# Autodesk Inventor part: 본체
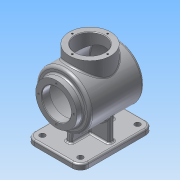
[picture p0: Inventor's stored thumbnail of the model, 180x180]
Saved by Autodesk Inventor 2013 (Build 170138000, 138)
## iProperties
Created: 2016-09
Part Number: 본체
Material: 알루미늄 6061
Document SubType Name: Modeling
Designer: Administrator
Density: 2.71 g/cm^3
Mass: 972.437 g
Surface Area: 1283.07 cm^2
Volume: 358.833 cm^3
Author: Administrator
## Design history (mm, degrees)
sketch "스케치1"
  geometry: L1 (-62, 38)-(-62, 27); L2 (-62, 27)-(-47, 27); L3 (-47, 27)-(-47, 47); L4 (-47, 47)-(46.661, 47); L5 (-62, 38)-(-50, 38); L6 (-50, 38)-(-50, 50); L7 (-50, 50)-(48.562, 50); L8 (57, 0)-(60, 0); A1 r 115 centre (-55, 0) between (60, 0) and (48.562, 50); A2 r 112 centre (-55, 0) between (57, 0) and (46.661, 47); 1 further point
  constraints: 16 end point, 4 parallel, 4 point on circle, 2 centre point, 2 perpendicular, 1 horizontal alignment, 1 point on line, 1 vertical
  dimensions: "d0" = 115 radius of A1; "d2" = 3 radial gap between concentric circles of A1 A2; "d3" = 54 diameter of L2 L8; "d4" = 76 diameter of L5 L8; "d5" = 100 diameter of L7 L8; "d6" = 94 diameter of L4 L8; "d7" = 15 distance between parallel lines of L3 L1; "d8" = 12 distance between parallel lines of L6 L1; "d9" = 110 distance from line of L8.end L6; "d51" = 50 distance from line of point (0, 0) L6
revolve "회전1" sketch "스케치1" stored, may be unused: angle "d11" = 90 deg
node "작업 평면1"
sketch "스케치2"
  geometry: L1 (50, 50)-(50, -50) reference; C1 r 38 at (0, 0); 1 further point
  constraints: 1 centre point, 1 coincident
  dimensions: "d13" = 76 diameter of C1; "d15" = 50 distance from line of C1.centre L1
extrude "돌출1" join sketch "스케치2" stored distance "d16" = 10; taper "d17" = 0 deg
hole "구멍1" diameter "d20" = 54; stored, may be unused: countersink angle "d24" = 90 deg, drill point angle "d26" = 118 deg; dims "d18" = 10, "d19" = 10, "d21" = 6, "d22" = 4, "d23" = 2, "d25" = 40
node "작업 평면2"
sketch "스케치6"
  geometry: L1 (-52.5, 50)-(52.5, 50); L2 (67.5, 35)-(67.5, -35); L3 (52.5, -50)-(-52.5, -50); L4 (-67.5, -35)-(-67.5, 35); C1 r 38 at (0, 0) reference; A1 r 15 centre (-52.5, 35) between (-52.5, 50) and (-67.5, 35); A2 r 15 centre (52.5, 35) between (67.5, 35) and (52.5, 50); A3 r 15 centre (52.5, -35) between (52.5, -50) and (67.5, -35); A4 r 15 centre (-52.5, -35) between (-67.5, -35) and (-52.5, -50); 3 further points
  constraints: 8 end point, 8 point on circle, 8 tangent, 4 centre point, 3 equal radius, 2 midpoint, 2 parallel, 1 horizontal, 1 horizontal alignment, 1 perpendicular, 1 vertical alignment
  dimensions: "d37" = 100 distance between parallel lines of L3 L1; "d39" = 135 distance between parallel lines of L4 L2; "d40" = 15 radius of A1
extrude "돌출3" join sketch "스케치6" distance "d41" = 10; taper "d42" = 0 deg
sketch "스케치8"
  geometry: L1 (-82, -35)-(-82, 35) reference; L2 (-82, 35)-(-72, 35) reference; L3 (-72, -35)-(-72, 35) reference; L4 (-82, -35)-(-72, -35) reference; L5 (-72, 40)-(-30, 40); L6 (-72, -40)-(-30, -40); L7 (-72, 40)-(-72, -40); A1 r 50 centre (0, 0) between (-30, 40) and (-30, -40) reference; 1 further point
  constraints: 6 end point, 3 parallel, 2 point on circle, 2 point on line, 1 perpendicular
  dimensions: "d43" = 40 distance from line of point (0, 0) L5
feature "리브1" sketch "스케치8" dims "d44" = 1, "d45" = 10, "d46" = 0, "d47" = 0, "d48" = 1, "d49" = 1
sketch "스케치10"
  geometry: L1 (-50, -50)-(48.562, -50) reference; L2 (52.5, -72)-(-52.5, -72) reference; L3 (-38.075, -50)-(-40, -72); L4 (38.075, -50)-(40, -72); L5 (-38.075, -72)-(40, -72); L6 (-40, -72)-(-38.075, -72); 1 further point
  constraints: 8 end point, 5 point on line, 2 collinear, 1 equal length
  dimensions: "d52" = 95 deg angle of L2 L3; "d53" = 40 horizontal distance of point (0, 0) L3.end; "d54" = 40 horizontal distance of point (0, 0) L4.end
feature "리브3" sketch "스케치10" dims "d61" = 1, "d62" = 10, "d63" = 0, "d64" = 0, "d65" = 1, "d66" = 1
sketch "스케치11"
  geometry: 1 further point
hole "구멍2" diameter "d69" = 10; stored, may be unused: countersink angle "d73" = 90 deg, drill point angle "d75" = 118 deg; dims "d67" = 10, "d68" = 10, "d70" = 6, "d71" = 4, "d72" = 2, "d74" = 40
hole "구멍3" diameter "d78" = 10; stored, may be unused: countersink angle "d82" = 90 deg, drill point angle "d84" = 118 deg; dims "d76" = 10, "d77" = 10, "d79" = 6, "d80" = 4, "d81" = 2, "d83" = 40
hole "구멍4" diameter "d87" = 10; stored, may be unused: countersink angle "d91" = 90 deg, drill point angle "d93" = 118 deg; dims "d85" = 10, "d86" = 10, "d88" = 6, "d89" = 4, "d90" = 2, "d92" = 40
hole "구멍5" diameter "d96" = 10; stored, may be unused: countersink angle "d100" = 90 deg, drill point angle "d102" = 118 deg; dims "d94" = 10, "d95" = 10, "d97" = 6, "d98" = 4, "d99" = 2, "d101" = 40
sketch "스케치12"
  geometry: 2 further points
  constraints: 1 vertical alignment
  dimensions: "d103" = 32.5 distance of point (0, 0) point (0, 32.5)
hole "구멍6" sketch "스케치12" at (0, 32.5) diameter "d104" = 3.242; stored, may be unused: countersink angle "d108" = 90 deg, drill point angle "d110" = 118 deg; dims "d105" = 8, "d106" = 4, "d107" = 2, "d109" = 10
sketch "스케치13"
  geometry: 2 further points
  constraints: 1 vertical alignment
  dimensions: "d114" = 32.5 distance of point (0, 0) point (0, 32.5)
hole "구멍7" sketch "스케치13" at (0, 32.5) diameter "d115" = 3.242; stored, may be unused: countersink angle "d119" = 90 deg, drill point angle "d121" = 118 deg; dims "d116" = 8, "d117" = 4, "d118" = 2, "d120" = 10
node "작업 평면3"
sketch "스케치14"
  geometry: 2 further points
  constraints: 1 coincident, 1 other
feature "엠보싱1" sketch "스케치14" dims "d125" = 0.5, "d126" = 0
chamfer "모따기1" distance "d127" = 1; stored, may be unused: second distance "d128" = 2, angle "d129" = 45 deg
fillet "모깎기1" dims "d130" = 2
fillet "모깎기2" dims "d131" = 5
fillet "모깎기3" dims "d132" = 3
fillet "모깎기4" dims "d133" = 3
fillet "모깎기5" dims "d134" = 3
node "솔리드1"
pattern_circular "원형 패턴1" dims angle "d112" = 360 deg
pattern_circular "원형 패턴2" dims angle "d123" = 360 deg
node "투영된 루프1"
other parameters: "d12" = 65, "d27" = -82
